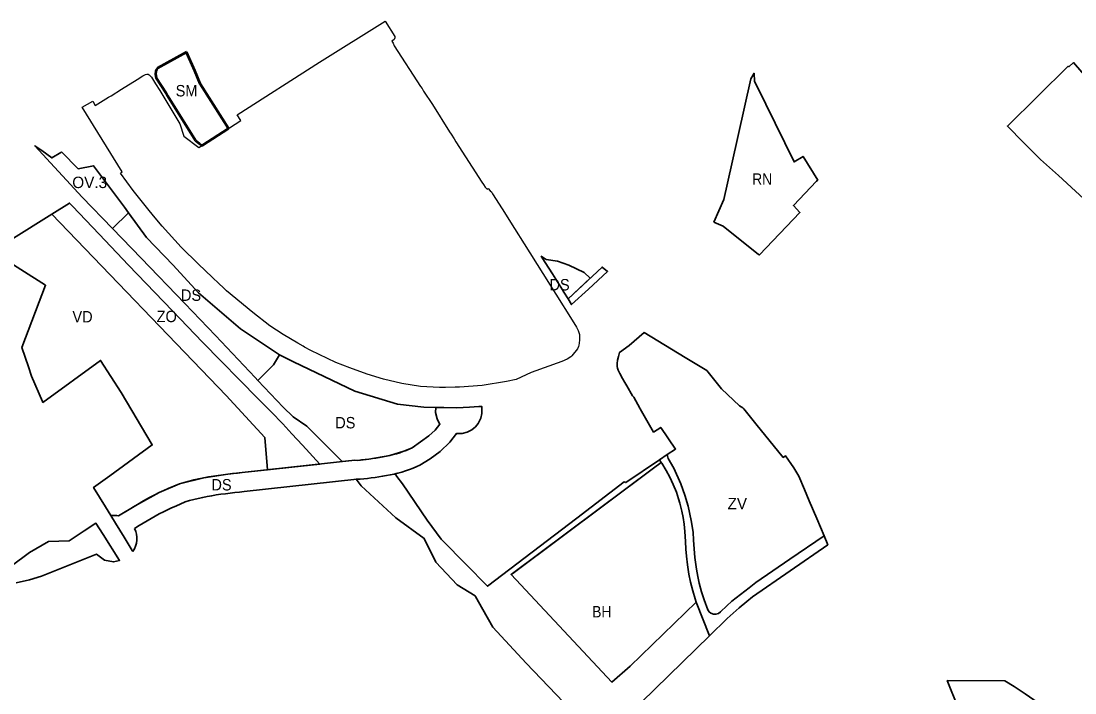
# Model space of a CAD drawing. Extents: x -650276 to -642489, y -1074311 to -1066658.
# Drawn here: x -647227 to -646121, y -1072417 to -1071711 of the extents above; entities that cross this region are included whole.
import ezdxf

# ---------------------------------------------------------------- set-up
doc = ezdxf.new("R2010")
doc.units = 0
doc.header["$LTSCALE"] = 4.8
for name, color, linetype, lineweight in [('1', 7, 'Continuous', 35), ('11', 7, 'Continuous', 35), ('15', 7, 'Continuous', 35), ('18', 7, 'Continuous', 35), ('24', 7, 'Continuous', 35), ('35', 7, 'Continuous', 35), ('40', 7, 'Continuous', 35), ('42', 7, 'Continuous', 35), ('48', 7, 'Continuous', 35), ('60', 7, 'Continuous', 53), ('61', 7, 'Continuous', 25), ('7', 7, 'Continuous', 35)]:
    doc.layers.add(name, color=color, linetype=linetype, lineweight=lineweight)
doc.layers.add('62', color=7, linetype='Continuous')

msp = doc.modelspace()

# ---------------------------------------------------------------- linework, layer by layer
at = {"layer": '1'}
for points in [[(-646102.04, -1071906.4), (-646068.317, -1071937.555), (-646062.91, -1071942.55), (-646002.93, -1071893.984), (-646026.64, -1071867.44), (-646043.49, -1071845.87), (-646077.32, -1071802.59), (-646087, -1071795), (-646104.5, -1071774.86), (-646122.16, -1071754.78), (-646127.12, -1071759.15), (-646127.84, -1071758.53), (-646191.57, -1071821.44), (-646174.69, -1071838.69), (-646156.59, -1071856.53), (-646137.74, -1071873.31)], [(-646606.848, -1072405.785), (-646587.666, -1072389.082), (-646518.208, -1072321.92), (-646519.417, -1072318.408), (-646522.007, -1072309.932), (-646524.282, -1072300.849), (-646526, -1072292.201), (-646527.5, -1072282.657), (-646528.566, -1072273.308), (-646529.182, -1072265.941), (-646529.607, -1072258.124), (-646530.188, -1072247.442), (-646530.892, -1072239.747), (-646531.93, -1072232.861), (-646533.286, -1072226.031), (-646535.344, -1072217.844), (-646536.772, -1072213.218), (-646539.168, -1072206.122), (-646539.168, -1072206.122), (-646542.484, -1072197.985), (-646546.09, -1072190.428), (-646549.793, -1072183.38), (-646554.56, -1072175.629), (-646555.051, -1072174.933), (-646563.299, -1072181.091), (-646710.684, -1072291.133), (-646712.634, -1072292.59)]]:
    msp.add_lwpolyline(points, close=True, dxfattribs=at)
at = {"layer": '11'}
for points in [[(-647184.81, -1071848.61), (-647185.62, -1071849.12), (-647194.96, -1071854.93), (-647205.62, -1071847.24), (-647212.66, -1071842.15), (-647163.08, -1071896.13), (-647131.146, -1071929.146)], [(-647131.146, -1071929.146), (-647114.479, -1071912.479), (-647118.79, -1071906.59), (-647151.07, -1071863.08), (-647167.15, -1071866.22), (-647184.81, -1071848.61)]]:
    msp.add_lwpolyline(points, dxfattribs=at)
at = {"layer": '15'}
for points in [[(-646652.864, -1072003.075), (-646617.21, -1071969.689), (-646611.438, -1071974.36), (-646631.409, -1071992.798), (-646649.112, -1072009.049)], [(-646529.182, -1072265.941), (-646528.566, -1072273.308), (-646527.5, -1072282.657), (-646526, -1072292.201), (-646524.282, -1072300.849), (-646522.007, -1072309.932), (-646519.417, -1072318.408), (-646518.208, -1072321.92), (-646504.244, -1072357.026), (-646485.656, -1072338.908), (-646473.069, -1072327.765), (-646465.227, -1072321.127), (-646459.03, -1072316.137), (-646380.12, -1072261.44), (-646384.056, -1072252.138), (-646420.085, -1072276.737), (-646455.557, -1072301.131), (-646462.79, -1072306.784), (-646480.923, -1072320.667), (-646486.273, -1072325.526), (-646492.813, -1072332.07), (-646494.794, -1072333.558), (-646497.569, -1072334.55), (-646500.244, -1072334.45), (-646503.018, -1072333.459), (-646504.802, -1072331.971), (-646506.189, -1072329.889), (-646509.954, -1072319.377), (-646512.729, -1072311.048), (-646515.305, -1072301.925), (-646516.692, -1072294.983), (-646518.079, -1072287.051), (-646519.756, -1072274.861), (-646521.051, -1072256.707), (-646521.646, -1072248.378), (-646523.628, -1072235.883), (-646526.798, -1072221.011), (-646530.167, -1072209.31), (-646534.527, -1072197.411), (-646541.822, -1072181.102), (-646547.606, -1072170.835), (-646548.676, -1072166.737), (-646556.693, -1072172.16), (-646555.051, -1072174.933), (-646554.56, -1072175.629), (-646549.793, -1072183.38), (-646546.09, -1072190.428), (-646542.484, -1072197.985), (-646539.168, -1072206.122), (-646536.772, -1072213.218), (-646535.344, -1072217.844), (-646533.286, -1072226.031), (-646531.93, -1072232.861), (-646530.892, -1072239.747), (-646530.188, -1072247.442), (-646529.607, -1072258.124)]]:
    msp.add_lwpolyline(points, close=True, dxfattribs=at)
at = {"layer": '18'}
for points in [[(-647053.43, -1071743.63), (-647083.97, -1071760.74), (-647084.95, -1071761.98), (-647085.71, -1071763.75), (-647086.19, -1071766.95), (-647085.25, -1071770.69), (-647074.99, -1071786.99), (-647073.19, -1071789.9), (-647044.12, -1071836.68)], [(-647009.514, -1071823.81), (-647016.12, -1071813.35), (-647039.14, -1071776.9), (-647044.83, -1071763.37), (-647053.43, -1071743.63)], [(-647044.12, -1071836.68), (-647040.2, -1071839.6), (-647037.23, -1071841.82), (-647009.514, -1071823.81)]]:
    msp.add_lwpolyline(points, dxfattribs=at)
at = {"layer": '24'}
for p, q in [((-646978.602, -1072088.66), (-646951.95, -1072116.84)), ((-647113.646, -1072224.274), (-647124.81, -1072231.168))]:
    msp.add_line(p, q, dxfattribs=at)
for points in [[(-646996.8, -1072034.35), (-647040.89, -1071996.58), (-647067.53, -1071967.54), (-647095.51, -1071938.39), (-647114.479, -1071912.479), (-647131.146, -1071929.146), (-647101.07, -1071960.24)], [(-647101.07, -1071960.24), (-647055.16, -1072007.74), (-647023.04, -1072041.63), (-646981.35, -1072085.77), (-646978.602, -1072088.66), (-646962.041, -1072072.379), (-646956.04, -1072061.95), (-646996.8, -1072034.35)], [(-646790.432, -1072129.195), (-646791.977, -1072122.305), (-646791.84, -1072117.172), (-646804.27, -1072116.98), (-646832.01, -1072113.66), (-646876.83, -1072100.12), (-646941.054, -1072069.172), (-646956.04, -1072061.95), (-646962.041, -1072072.379), (-646978.602, -1072088.66)], [(-646816.74, -1072159.571), (-646799, -1072147), (-646792.58, -1072140.847), (-646787.481, -1072134.643), (-646790.343, -1072129.36), (-646791.977, -1072122.305), (-646791.84, -1072117.172), (-646783.449, -1072117.302), (-646769.668, -1072117.517), (-646756.298, -1072117), (-646746.547, -1072116.221), (-646743.596, -1072115.985), (-646743.411, -1072123.612), (-646744.554, -1072128.415), (-646747.39, -1072134.069), (-646750.164, -1072137.467), (-646753.929, -1072140.612), (-646758.736, -1072143.137), (-646763.959, -1072144.535), (-646770.057, -1072144.677), (-646777.129, -1072153.576), (-646787.223, -1072163.402), (-646797.713, -1072171.151), (-646808.466, -1072177.78)], [(-646808.466, -1072177.78), (-646797.713, -1072171.151), (-646787.223, -1072163.402), (-646777.129, -1072153.576), (-646770.057, -1072144.677), (-646763.959, -1072144.535), (-646758.736, -1072143.137), (-646753.929, -1072140.612), (-646750.164, -1072137.467), (-646747.39, -1072134.069), (-646744.554, -1072128.415), (-646743.411, -1072123.612), (-646743.596, -1072115.985), (-646746.547, -1072116.221), (-646756.298, -1072117), (-646769.668, -1072117.517), (-646783.449, -1072117.302), (-646791.84, -1072117.172), (-646791.977, -1072122.305), (-646790.343, -1072129.36), (-646787.481, -1072134.643), (-646792.58, -1072140.847), (-646799, -1072147), (-646816.74, -1072159.571)], [(-646951.95, -1072116.84), (-646941.45, -1072126.84), (-646927.14, -1072136.74), (-646891.05, -1072172.79), (-646890.044, -1072174.056), (-646876.712, -1072172.592), (-646873.495, -1072172.799), (-646862.09, -1072171.444), (-646840.102, -1072167.623), (-646825.169, -1072163.164), (-646816.74, -1072159.571), (-646799, -1072147), (-646792.58, -1072140.847), (-646787.481, -1072134.643), (-646790.432, -1072129.195)], [(-647124.81, -1072231.168), (-647113.646, -1072224.274), (-647109.342, -1072221.634), (-647104.989, -1072219.005), (-647100.583, -1072216.405), (-647096.114, -1072213.845), (-647091.574, -1072211.346), (-647086.955, -1072208.921), (-647082.249, -1072206.591), (-647077.456, -1072204.373), (-647072.72, -1072202.352), (-647060.973, -1072197.439), (-647055.906, -1072195.893), (-647050.82, -1072194.5), (-647045.722, -1072193.245), (-647040.618, -1072192.117), (-647035.515, -1072191.104), (-647030.417, -1072190.192), (-647025.33, -1072189.37), (-647020.254, -1072188.623), (-647015.192, -1072187.939), (-647010.148, -1072187.308), (-647005.124, -1072186.715), (-647000.12, -1072186.148), (-646995.137, -1072185.597), (-646876.712, -1072172.592), (-646873.495, -1072172.799), (-646869.667, -1072172.366), (-646865.866, -1072171.917), (-646862.09, -1072171.444), (-646858.343, -1072170.937), (-646854.627, -1072170.389), (-646850.941, -1072169.791), (-646847.291, -1072169.137), (-646843.678, -1072168.416), (-646840.102, -1072167.623), (-646836.573, -1072166.751), (-646833.091, -1072165.791), (-646829.66, -1072164.739), (-646826.287, -1072163.588), (-646822.975, -1072162.332), (-646819.733, -1072160.968), (-646816.74, -1072159.571)], [(-646816.74, -1072159.571), (-646819.733, -1072160.968), (-646822.975, -1072162.332), (-646826.287, -1072163.588), (-646829.66, -1072164.739), (-646833.091, -1072165.791), (-646836.573, -1072166.751), (-646840.102, -1072167.623), (-646843.678, -1072168.416), (-646847.291, -1072169.137), (-646850.941, -1072169.791), (-646854.627, -1072170.389), (-646858.343, -1072170.937), (-646862.09, -1072171.444), (-646865.866, -1072171.917), (-646869.667, -1072172.366), (-646873.495, -1072172.799), (-646876.712, -1072172.592), (-646995.137, -1072185.597), (-647000.12, -1072186.148), (-647005.124, -1072186.715), (-647010.148, -1072187.308), (-647015.192, -1072187.939), (-647020.254, -1072188.623), (-647025.33, -1072189.37), (-647030.417, -1072190.192), (-647035.515, -1072191.104), (-647040.618, -1072192.117), (-647045.722, -1072193.245), (-647050.82, -1072194.5), (-647055.906, -1072195.893), (-647060.973, -1072197.439), (-647072.72, -1072202.352), (-647077.456, -1072204.373), (-647082.249, -1072206.591), (-647086.955, -1072208.921), (-647091.574, -1072211.346), (-647096.114, -1072213.845), (-647100.583, -1072216.405), (-647104.989, -1072219.005), (-647109.342, -1072221.634), (-647113.646, -1072224.274)], [(-646808.466, -1072177.78), (-646811.621, -1072179.254), (-646815.549, -1072180.906), (-646819.509, -1072182.408), (-646823.496, -1072183.769), (-646827.501, -1072184.997), (-646831.517, -1072186.103), (-646835.538, -1072187.097), (-646839.556, -1072187.988), (-646843.569, -1072188.789), (-646847.575, -1072189.507), (-646851.567, -1072190.155), (-646855.545, -1072190.741), (-646859.506, -1072191.276), (-646863.448, -1072191.771), (-646867.371, -1072192.234), (-646871.271, -1072192.675), (-646874.517, -1072192.471), (-646992.937, -1072205.475), (-646997.894, -1072206.024), (-647002.826, -1072206.583), (-647007.734, -1072207.162), (-647012.612, -1072207.773), (-647017.46, -1072208.427), (-647022.278, -1072209.136), (-647027.061, -1072209.91), (-647031.807, -1072210.758), (-647036.512, -1072211.693), (-647041.174, -1072212.723), (-647045.786, -1072213.858), (-647050.344, -1072215.107), (-647054.841, -1072216.479), (-647064.868, -1072220.746), (-647069.33, -1072222.651), (-647073.611, -1072224.631), (-647077.867, -1072226.739), (-647082.102, -1072228.962), (-647086.322, -1072231.285), (-647090.531, -1072233.695), (-647094.737, -1072236.177), (-647098.944, -1072238.718), (-647103.164, -1072241.306), (-647108.131, -1072244.373)], [(-646874.517, -1072192.471), (-646871.271, -1072192.675), (-646867.371, -1072192.234), (-646863.448, -1072191.771), (-646859.506, -1072191.276), (-646855.545, -1072190.741), (-646851.567, -1072190.155), (-646847.575, -1072189.507), (-646843.569, -1072188.789), (-646839.556, -1072187.988), (-646835.538, -1072187.097), (-646831.517, -1072186.103), (-646827.501, -1072184.997), (-646823.496, -1072183.769), (-646819.509, -1072182.408), (-646815.549, -1072180.906), (-646811.621, -1072179.254), (-646808.466, -1072177.78)], [(-647108.131, -1072244.373), (-647103.164, -1072241.306), (-647098.944, -1072238.718), (-647094.737, -1072236.177), (-647090.531, -1072233.695), (-647086.322, -1072231.285), (-647082.102, -1072228.962), (-647077.867, -1072226.739), (-647073.611, -1072224.631), (-647069.33, -1072222.651), (-647064.868, -1072220.746), (-647054.841, -1072216.479), (-647050.344, -1072215.107), (-647045.786, -1072213.858), (-647041.174, -1072212.723), (-647036.512, -1072211.693), (-647031.807, -1072210.758), (-647027.061, -1072209.91), (-647022.278, -1072209.136), (-647017.46, -1072208.427), (-647012.612, -1072207.773), (-647007.734, -1072207.162), (-647002.826, -1072206.583), (-646997.894, -1072206.024), (-646992.937, -1072205.475), (-646874.517, -1072192.471)], [(-647109.812, -1072268.588), (-647110.55, -1072267.42), (-647119.07, -1072253.56), (-647128.07, -1072238.83), (-647133, -1072230.754)], [(-647133, -1072230.754), (-647128.07, -1072238.83), (-647119.07, -1072253.56), (-647110.55, -1072267.42), (-647109.812, -1072268.588)], [(-647232.368, -1072301.4), (-647218.5, -1072298.335), (-647205.975, -1072294.599), (-647148.171, -1072271.47), (-647139.697, -1072277.484), (-647130.12, -1072279.44), (-647123.774, -1072277.899), (-647141.05, -1072250.54), (-647148.71, -1072238.76), (-647148.71, -1072238.76), (-647160.91, -1072246.82), (-647176.7, -1072257.24), (-647198.3, -1072258.09), (-647218.35, -1072269.67), (-647237.6, -1072283.78)]]:
    msp.add_lwpolyline(points, dxfattribs=at)
msp.add_lwpolyline([(-646652.18, -1071967.73), (-646636.01, -1071975.35), (-646629.655, -1071981.343), (-646652.864, -1072003.075), (-646657.32, -1071995.98), (-646658.79, -1071993.62), (-646669.31, -1071976.77), (-646676.79, -1071964.97), (-646681.07, -1071958.16), (-646675.99, -1071961.64), (-646663.87, -1071963.26)], close=True, dxfattribs=at)
for centre, start, end in [((-646767.624, -1072120.384), 264.28146, 264.89913), ((-647130.12, -1072255.012), 77.44425, 96.77054), ((-647130.12, -1072255.012), 77.44425, 96.77054), ((-647130.12, -1072255.012), 326.23773, 25.81772), ((-647130.12, -1072255.012), 326.23773, 25.81772)]:
    msp.add_arc(centre, 24.428, start, end, dxfattribs=at)
at = {"layer": '35'}
msp.add_lwpolyline([(-647249.92, -1071958.12), (-647201.53, -1071988.71), (-647226.41, -1072054.11), (-647219.64, -1072074.29), (-647216.23, -1072084.14), (-647204.78, -1072110.92), (-647204.38, -1072111.87), (-647143.76, -1072067.69), (-647122.33, -1072101.34), (-647089.54, -1072156.53), (-647134.17, -1072188.95), (-647151.05, -1072201.21), (-647138.65, -1072221.5), (-647133, -1072230.754), (-647124.81, -1072231.168), (-647104.989, -1072219.005), (-647082.249, -1072206.591), (-647060.973, -1072197.439), (-647035.515, -1072191.104), (-647010.148, -1072187.308), (-646995.137, -1072185.597), (-646968.503, -1072182.672), (-646971.283, -1072148.82), (-647011.762, -1072104.502), (-647194.903, -1071913.941), (-647238.1, -1071941)], dxfattribs=at)
at = {"layer": '40'}
msp.add_lwpolyline([(-646507.28, -1072078.4), (-646530.073, -1072064.559), (-646573.05, -1072038.46), (-646588.75, -1072052.06), (-646598.827, -1072059.244), (-646599.86, -1072063.71), (-646601, -1072067.55), (-646601.42, -1072071.01), (-646601.16, -1072074.07), (-646600.8, -1072075.94), (-646600.22, -1072077.86), (-646598.67, -1072081.55), (-646595.86, -1072086.82), (-646593.13, -1072091.01), (-646591.02, -1072094.4), (-646585.08, -1072104.81), (-646583.9, -1072106.42), (-646577.41, -1072117.76), (-646577.08, -1072118.7), (-646563.11, -1072143.03), (-646555.49, -1072138.17), (-646539.94, -1072160.83), (-646548.676, -1072166.737), (-646547.606, -1072170.835), (-646541.822, -1072181.102), (-646534.527, -1072197.411), (-646530.167, -1072209.31), (-646526.798, -1072221.011), (-646523.628, -1072235.883), (-646521.646, -1072248.378), (-646521.051, -1072256.707), (-646519.756, -1072274.861), (-646518.079, -1072287.051), (-646516.692, -1072294.983), (-646515.305, -1072301.925), (-646512.729, -1072311.048), (-646509.954, -1072319.377), (-646506.189, -1072329.889), (-646504.802, -1072331.971), (-646503.018, -1072333.459), (-646500.244, -1072334.45), (-646497.569, -1072334.55), (-646494.794, -1072333.558), (-646492.813, -1072332.07), (-646486.273, -1072325.526), (-646480.923, -1072320.667), (-646462.79, -1072306.784), (-646455.557, -1072301.131), (-646420.085, -1072276.737), (-646384.056, -1072252.138), (-646391.77, -1072233.91), (-646399.6, -1072215.39), (-646404.67, -1072203.42), (-646410.68, -1072189.36), (-646415.84, -1072180.43), (-646424.56, -1072167.96), (-646426.98, -1072169.74), (-646455.75, -1072134.29), (-646468.35, -1072118.76), (-646469.41, -1072117.44), (-646472.72, -1072115.38), (-646491.69, -1072097.45)], close=True, dxfattribs=at)
at = {"layer": '42'}
msp.add_lwpolyline([(-647011.762, -1072104.502), (-646971.283, -1072148.82), (-646968.503, -1072182.672), (-646942.928, -1072179.864), (-646913.373, -1072176.618), (-646931.653, -1072156.802), (-646942.78, -1072144.74), (-646952.48, -1072134.22), (-646964.8, -1072121.83), (-646977.59, -1072108.96), (-646978.45, -1072108.09), (-647036.8, -1072048.41), (-647068.31, -1072015.68), (-647114.59, -1071967.77), (-647145.38, -1071935), (-647173.14, -1071905.45), (-647174.57, -1071904.06), (-647176.32, -1071902.3), (-647194.903, -1071913.941)], close=True, dxfattribs=at)
msp.add_lwpolyline([(-646575.792, -1072426.789), (-646504.244, -1072357.026), (-646518.208, -1072321.92), (-646587.666, -1072389.082), (-646606.848, -1072405.785), (-646712.634, -1072292.59), (-646563.299, -1072181.091), (-646555.051, -1072174.933), (-646556.693, -1072172.16), (-646592.2, -1072196.17), (-646593.85, -1072195.48), (-646643.55, -1072233.5), (-646737.449, -1072305.019), (-646738.951, -1072303.49), (-646758.684, -1072283.41), (-646785.958, -1072255.505), (-646800.76, -1072235.668), (-646826.893, -1072197.582), (-646832.718, -1072189.697), (-646834.279, -1072186.818), (-646833.373, -1072186.562), (-646835.538, -1072187.097), (-646839.556, -1072187.988), (-646843.569, -1072188.789), (-646847.575, -1072189.507), (-646851.567, -1072190.155), (-646855.545, -1072190.741), (-646859.506, -1072191.276), (-646863.448, -1072191.771), (-646867.371, -1072192.234), (-646871.271, -1072192.675), (-646874.517, -1072192.471), (-646875.509, -1072192.58), (-646870.21, -1072199.51), (-646833.75, -1072233.32), (-646803.98, -1072254.74), (-646791.59, -1072279.78), (-646769.24, -1072303.65), (-646750.58, -1072315.02), (-646750.12, -1072315.82), (-646742.32, -1072329.62), (-646731.82, -1072348.2), (-646696.83, -1072385.81), (-646618.158, -1072468.098)], dxfattribs=at)
at = {"layer": '48'}
msp.add_lwpolyline([(-646110.61, -1072477.49), (-646153.49, -1072431.54), (-646172.81, -1072418.2), (-646184.449, -1072410.256), (-646194.19, -1072404.62), (-646254.75, -1072404.25), (-646243.17, -1072432.88), (-646282.47, -1072474.34), (-646328.45, -1072504.81), (-646307.6, -1072547.74), (-646236.97, -1072678.31), (-646171.72, -1072803.51), (-646052.58, -1072737.82)], dxfattribs=at)
at = {"layer": '60'}
for points in [[(-647053.43, -1071743.63), (-647083.97, -1071760.74), (-647084.95, -1071761.98), (-647085.71, -1071763.75), (-647086.19, -1071766.95), (-647085.25, -1071770.69), (-647074.99, -1071786.99)], [(-647009.514, -1071823.81), (-647016.12, -1071813.35), (-647039.14, -1071776.9), (-647044.83, -1071763.37), (-647053.43, -1071743.63)], [(-647074.99, -1071786.99), (-647073.19, -1071789.9), (-647044.12, -1071836.68)], [(-647044.12, -1071836.68), (-647040.2, -1071839.6), (-647037.23, -1071841.82), (-647009.514, -1071823.81)]]:
    msp.add_lwpolyline(points, dxfattribs=at)
at = {"layer": '61'}
for points in [[(-646641.16, -1072049.51), (-646641.59, -1072051.75), (-646642.05, -1072053.14), (-646643.11, -1072055.41), (-646648.78, -1072062.89), (-646650.1, -1072063.91), (-646653.86, -1072066.41), (-646659.309, -1072068.883), (-646691.77, -1072080.37), (-646707.5, -1072087.64), (-646717.55, -1072090), (-646742.95, -1072093.96), (-646767.01, -1072095.86), (-646771.52, -1072095.92), (-646781.75, -1072096.04), (-646784.76, -1072096.01), (-646787.8, -1072096.24), (-646807.9, -1072095.03), (-646827.46, -1072092.09), (-646846.81, -1072087.28), (-646863.68, -1072082.09), (-646881.98, -1072075.61), (-646896.84, -1072069.83), (-646922.95, -1072057.25), (-646929.53, -1072053.65), (-646931, -1072052.81), (-646936.81, -1072049.5), (-646952.07, -1072040.55), (-646966.13, -1072031.23), (-646983.88, -1072017.52), (-647011.61, -1071994.42), (-647015.13, -1071991.01), (-647019.3, -1071987.12), (-647026.77, -1071980.29), (-647041.08, -1071966.71), (-647059.01, -1071948.52), (-647079.15, -1071926.49), (-647088.04, -1071915.77), (-647094.25, -1071908.29), (-647109.58, -1071889.27), (-647123, -1071870.89), (-647121.15, -1071869.68), (-647162.98, -1071801.68), (-647152.08, -1071795.15), (-647149.32, -1071799.92), (-647135.34, -1071791.17), (-647132.63, -1071789.47), (-647121.76, -1071782.65), (-647119.06, -1071780.95), (-647108.21, -1071774.17), (-647105.49, -1071772.47), (-647099.39, -1071768.65), (-647096.58, -1071767.23), (-647095.35, -1071766.89), (-647093.94, -1071766.95), (-647092.65, -1071767.48), (-647091.55, -1071768.46), (-647090.45, -1071769.99), (-647085.97, -1071777.09), (-647081.6, -1071784.03), (-647071.99, -1071799.81), (-647066.76, -1071808.54), (-647060.7, -1071819.12), (-647056.31, -1071832.13), (-647040.52, -1071843.958), (-647037.23, -1071841.82), (-646996.65, -1071815.45), (-647000.4, -1071809.69), (-646913.82, -1071754.1), (-646845.08, -1071711.06), (-646834.86, -1071727.2), (-646834.66, -1071728.69), (-646835.33, -1071730.32), (-646837.92, -1071732.14), (-646836.62, -1071734.14), (-646835.35, -1071737.24), (-646807.7, -1071779.69), (-646806.22, -1071781.97), (-646804.6, -1071784.61), (-646795.36, -1071798.85), (-646777.21, -1071827.55), (-646775.63, -1071830.04), (-646772.5, -1071834.88), (-646770.65, -1071837.91), (-646743.34, -1071880.3), (-646741.81, -1071882.7), (-646740.07, -1071885.5), (-646737.81, -1071887.58), (-646736.61, -1071887.04), (-646734.75, -1071889.65), (-646733.38, -1071890.49), (-646732.05, -1071892.58), (-646721.96, -1071908.47), (-646709.19, -1071928.91), (-646698.88, -1071945.32), (-646665.78, -1071998.02), (-646648.65, -1072025.26), (-646644.03, -1072032.61), (-646642.27, -1072036.3)], [(-646642.27, -1072036.3), (-646640.88, -1072040.43), (-646640.7, -1072041.21), (-646640.73, -1072046.02), (-646640.73, -1072046.02), (-646641.16, -1072049.51)]]:
    msp.add_lwpolyline(points, dxfattribs=at)
at = {"layer": '7'}
for points in [[(-646453.04, -1071956.3), (-646451.87, -1071956.88), (-646409.4, -1071912.17), (-646416.2, -1071904.81), (-646391.83, -1071879.32), (-646390.732, -1071878.171), (-646405.99, -1071853.26), (-646415.46, -1071859.05), (-646445.115, -1071798.418), (-646456.96, -1071774.2), (-646457.52, -1071765.98), (-646461.09, -1071771.76), (-646480.81, -1071861.18), (-646489.34, -1071898.61), (-646499.741, -1071922.455)], [(-646499.741, -1071922.455), (-646490.111, -1071926.754), (-646453.04, -1071956.3)]]:
    msp.add_lwpolyline(points, dxfattribs=at)

# ---------------------------------------------------------------- texts
at = {"layer": '62'}
for s, width, p in [('SM', 0.95, (-647064.938, -1071790.245)), ('RN', 0.9, (-646459.448, -1071883.14)), ('DS', 0.95, (-646672.386, -1071994.148)), ('DS', 0.95, (-647059.386, -1072005.148)), ('VD', 0.95, (-647173.311, -1072027.838)), ('ZO', 0.95, (-647084.886, -1072027.486)), ('DS', 0.95, (-646897.386, -1072139.148)), ('DS', 0.95, (-647027.378, -1072204.379)), ('BH', 0.9, (-646627.48, -1072337.818))]:
    msp.add_text(s, height=12, dxfattribs=dict(at, width=width)).set_placement(p)
for s, p in [('OV.3', (-647173.505, -1071886.6)), ('ZV', (-646485.386, -1072224.148))]:
    msp.add_text(s, height=12, dxfattribs=at).set_placement(p)

doc.saveas('drawing.dxf')
